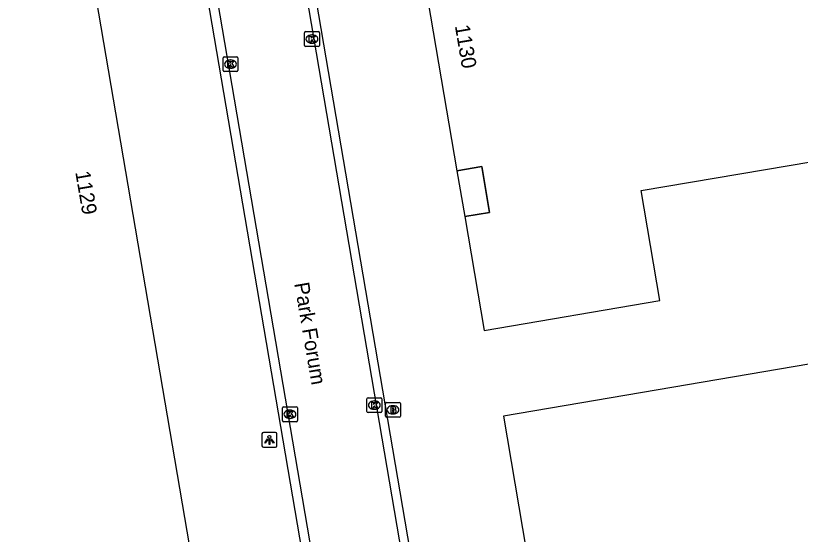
# Model space of a CAD drawing. Extents: x 154324 to 155743, y 382939 to 384183.
# Drawn here: x 154879.7 to 154932.5, y 383550.2 to 383585.1 of the extents above; entities that cross this region are included whole.
import ezdxf

# ---------------------------------------------------------------- set-up
doc = ezdxf.new("R2010")
doc.units = 0
for name, color, linetype in [('IMGEO_Brandkraan', 7, 'Continuous'), ('IMGEO_Kolk', 7, 'Continuous'), ('IMGEO_Lichtpunt', 7, 'Continuous'), ('IMGEO_Openbare_ruimte_label', 7, 'Continuous'), ('IMGEO_Pand', 7, 'Continuous'), ('IMGEO_Pand_nummerreeks', 7, 'Continuous'), ('IMGEO_Pand_overbouw', 7, 'Continuous'), ('IMGEO_Rijbaan_lokaal_gesloten', 7, 'Continuous'), ('IMGEO_Rijbaan_lokaal_open', 7, 'Continuous')]:
    doc.layers.add(name, color=color, linetype=linetype)

msp = doc.modelspace()

# ---------------------------------------------------------------- linework, layer by layer
at = {"layer": 'IMGEO_Brandkraan'}
for p, q in [((154904.624, 383558.127), (154904.624, 383558.979)), ((154904.699, 383559.053), (154905.551, 383559.053)), ((154905.112, 383558.833), (154905.137, 383558.833)), ((154905.625, 383558.979), (154905.625, 383558.127)), ((154905.551, 383558.053), (154904.699, 383558.053)), ((154905.135, 383558.273), (154905.11, 383558.273))]:
    msp.add_line(p, q, dxfattribs=at)
for points in [[(154904.624, 383558.127), (154904.624, 383558.979)], [(154904.699, 383559.053), (154905.551, 383559.053)], [(154904.972, 383558.753), (154904.972, 383558.353), (154905.185, 383558.353)], [(154905.203, 383558.753), (154904.972, 383558.753)], [(154905.151, 383558.672), (154905.097, 383558.672), (154905.097, 383558.596)], [(154905.097, 383558.596), (154905.15, 383558.596)], [(154905.625, 383558.979), (154905.625, 383558.127)], [(154905.551, 383558.053), (154904.699, 383558.053)], [(154905.159, 383558.52), (154905.097, 383558.52), (154905.097, 383558.439)], [(154905.097, 383558.439), (154905.159, 383558.439)]]:
    msp.add_lwpolyline(points, dxfattribs=at)
for centre, radius, start, end in [((154904.701, 383558.977), 0.0765, 91.552, 178.448), ((154904.701, 383558.977), 0.0765, 91.552, 178.448), ((154905.152, 383558.634), 0.0379, 267.8285, 90.9355), ((154905.207, 383558.608), 0.145, 59.4692, 91.5367), ((154905.232, 383558.655), 0.0922, 285.5137, 58.1501), ((154905.237, 383558.463), 0.105, 301.3115, 78.989), ((154905.549, 383558.977), 0.0765, 1.552, 88.448), ((154905.549, 383558.977), 0.0765, 1.552, 88.448), ((154904.701, 383558.129), 0.0765, 181.552, 268.448), ((154904.701, 383558.129), 0.0765, 181.552, 268.448), ((154905.16, 383558.479), 0.0404, 269.8759, 90.5077), ((154905.191, 383558.604), 0.251, 268.6676, 293.5347), ((154905.549, 383558.129), 0.0765, 271.552, 358.448), ((154905.549, 383558.129), 0.0765, 271.552, 358.448)]:
    msp.add_arc(centre, radius, start, end, dxfattribs=at)
for centre, major_axis, ratio, start_param, end_param in [((154905.111, 383558.553), (-0.387, 0.002), 0.722429, 4.712389, 7.853982), ((154905.136, 383558.553), (-0.39, 0.002), 0.717154, 1.570796, 4.712389)]:
    msp.add_ellipse(centre, major_axis=major_axis, ratio=ratio, start_param=start_param, end_param=end_param, dxfattribs=at)
at = {"layer": 'IMGEO_Kolk'}
for p, q in [((154899.172, 383583.091), (154899.172, 383583.943)), ((154899.247, 383584.017), (154900.099, 383584.017)), ((154900.173, 383583.943), (154900.173, 383583.091)), ((154899.66, 383583.797), (154899.685, 383583.797)), ((154900.099, 383583.017), (154899.247, 383583.017)), ((154899.683, 383583.237), (154899.658, 383583.237)), ((154893.77, 383582.329), (154894.622, 383582.329)), ((154893.695, 383581.403), (154893.695, 383582.255)), ((154894.183, 383582.109), (154894.208, 383582.109)), ((154894.696, 383582.255), (154894.696, 383581.403)), ((154894.622, 383581.329), (154893.77, 383581.329)), ((154894.206, 383581.549), (154894.181, 383581.549)), ((154903.373, 383558.443), (154903.373, 383559.295)), ((154903.448, 383559.369), (154904.3, 383559.369)), ((154903.861, 383559.149), (154903.886, 383559.149)), ((154904.374, 383559.295), (154904.374, 383558.443)), ((154897.693, 383557.83), (154897.693, 383558.682)), ((154897.768, 383558.756), (154898.62, 383558.756)), ((154898.694, 383558.682), (154898.694, 383557.83)), ((154903.884, 383558.589), (154903.859, 383558.589)), ((154898.181, 383558.536), (154898.206, 383558.536)), ((154904.3, 383558.369), (154903.448, 383558.369)), ((154898.62, 383557.756), (154897.768, 383557.756)), ((154898.204, 383557.976), (154898.179, 383557.976))]:
    msp.add_line(p, q, dxfattribs=at)
for points in [[(154899.172, 383583.091), (154899.172, 383583.943)], [(154899.247, 383584.017), (154900.099, 383584.017)], [(154900.173, 383583.943), (154900.173, 383583.091)], [(154899.493, 383583.717), (154899.616, 383583.717), (154899.616, 383583.566), (154899.746, 383583.717), (154899.91, 383583.717), (154899.764, 383583.566), (154899.917, 383583.317), (154899.765, 383583.317), (154899.68, 383583.481), (154899.616, 383583.414), (154899.616, 383583.317), (154899.493, 383583.317), (154899.493, 383583.717)], [(154900.099, 383583.017), (154899.247, 383583.017)], [(154893.77, 383582.329), (154894.622, 383582.329)], [(154893.695, 383581.403), (154893.695, 383582.255)], [(154894.016, 383582.029), (154894.139, 383582.029), (154894.139, 383581.878), (154894.269, 383582.029), (154894.433, 383582.029), (154894.287, 383581.878), (154894.44, 383581.629), (154894.288, 383581.629), (154894.203, 383581.793), (154894.139, 383581.726), (154894.139, 383581.629), (154894.016, 383581.629), (154894.016, 383582.029)], [(154894.696, 383582.255), (154894.696, 383581.403)], [(154894.622, 383581.329), (154893.77, 383581.329)], [(154903.373, 383558.443), (154903.373, 383559.295)], [(154903.448, 383559.369), (154904.3, 383559.369)], [(154904.374, 383559.295), (154904.374, 383558.443)], [(154897.693, 383557.83), (154897.693, 383558.682)], [(154897.768, 383558.756), (154898.62, 383558.756)], [(154898.694, 383558.682), (154898.694, 383557.83)], [(154903.694, 383559.069), (154903.817, 383559.069), (154903.817, 383558.918), (154903.947, 383559.069), (154904.111, 383559.069), (154903.965, 383558.918), (154904.118, 383558.669), (154903.966, 383558.669), (154903.881, 383558.833), (154903.817, 383558.766), (154903.817, 383558.669), (154903.694, 383558.669), (154903.694, 383559.069)], [(154898.014, 383558.456), (154898.137, 383558.456), (154898.137, 383558.305), (154898.267, 383558.456), (154898.431, 383558.456), (154898.285, 383558.305), (154898.438, 383558.056), (154898.286, 383558.056), (154898.201, 383558.22), (154898.137, 383558.153), (154898.137, 383558.056), (154898.014, 383558.056), (154898.014, 383558.456)], [(154904.3, 383558.369), (154903.448, 383558.369)], [(154898.62, 383557.756), (154897.768, 383557.756)]]:
    msp.add_lwpolyline(points, dxfattribs=at)
for centre, start, end in [((154899.249, 383583.941), 91.552, 178.448), ((154899.249, 383583.941), 91.552, 178.448), ((154900.097, 383583.941), 1.552, 88.448), ((154900.097, 383583.941), 1.552, 88.448), ((154899.249, 383583.093), 181.552, 268.448), ((154899.249, 383583.093), 181.552, 268.448), ((154900.097, 383583.093), 271.552, 358.448), ((154900.097, 383583.093), 271.552, 358.448), ((154893.772, 383582.253), 91.552, 178.448), ((154893.772, 383582.253), 91.552, 178.448), ((154894.62, 383582.253), 1.552, 88.448), ((154894.62, 383582.253), 1.552, 88.448), ((154893.772, 383581.405), 181.552, 268.448), ((154893.772, 383581.405), 181.552, 268.448), ((154894.62, 383581.405), 271.552, 358.448), ((154894.62, 383581.405), 271.552, 358.448), ((154903.45, 383559.293), 91.552, 178.448), ((154903.45, 383559.293), 91.552, 178.448), ((154904.298, 383559.293), 1.552, 88.448), ((154904.298, 383559.293), 1.552, 88.448), ((154897.77, 383558.68), 91.552, 178.448), ((154897.77, 383558.68), 91.552, 178.448), ((154898.618, 383558.68), 1.552, 88.448), ((154898.618, 383558.68), 1.552, 88.448), ((154903.45, 383558.445), 181.552, 268.448), ((154903.45, 383558.445), 181.552, 268.448), ((154904.298, 383558.445), 271.552, 358.448), ((154904.298, 383558.445), 271.552, 358.448), ((154897.77, 383557.832), 181.552, 268.448), ((154897.77, 383557.832), 181.552, 268.448), ((154898.618, 383557.832), 271.552, 358.448), ((154898.618, 383557.832), 271.552, 358.448)]:
    msp.add_arc(centre, 0.0765, start, end, dxfattribs=at)
for centre, major_axis, ratio, start_param, end_param in [((154899.659, 383583.517), (-0.387, 0.002), 0.722429, 4.712389, 7.853982), ((154899.684, 383583.517), (-0.39, 0.002), 0.717154, 1.570796, 4.712389), ((154894.182, 383581.829), (-0.387, 0.002), 0.722429, 4.712389, 7.853982), ((154894.207, 383581.829), (-0.39, 0.002), 0.717154, 1.570796, 4.712389), ((154903.86, 383558.869), (-0.387, 0.002), 0.722429, 4.712389, 7.853982), ((154903.885, 383558.869), (-0.39, 0.002), 0.717154, 1.570796, 4.712389), ((154898.18, 383558.256), (-0.387, 0.002), 0.722429, 4.712389, 7.853982), ((154898.205, 383558.256), (-0.39, 0.002), 0.717154, 1.570796, 4.712389)]:
    msp.add_ellipse(centre, major_axis=major_axis, ratio=ratio, start_param=start_param, end_param=end_param, dxfattribs=at)
at = {"layer": 'IMGEO_Lichtpunt'}
for p, q in [((154897.213, 383557.031), (154896.405, 383557.031)), ((154897.213, 383557.031), (154896.405, 383557.031)), ((154896.311, 383556.936), (154896.311, 383556.129)), ((154896.311, 383556.936), (154896.311, 383556.129)), ((154897.307, 383556.129), (154897.307, 383556.936)), ((154897.307, 383556.129), (154897.307, 383556.936)), ((154896.405, 383556.035), (154897.213, 383556.035)), ((154896.405, 383556.035), (154897.213, 383556.035))]:
    msp.add_line(p, q, dxfattribs=at)
for points in [[(154896.685, 383556.6), (154896.724, 383556.572), (154896.536, 383556.31), (154896.498, 383556.337), (154896.685, 383556.6)], [(154896.787, 383556.552), (154896.834, 383556.552), (154896.834, 383556.23), (154896.787, 383556.23), (154896.787, 383556.552)], [(154896.897, 383556.572), (154896.935, 383556.599), (154897.122, 383556.337), (154897.083, 383556.309), (154896.897, 383556.572)]]:
    msp.add_lwpolyline(points, dxfattribs=at)
msp.add_circle((154896.81, 383556.734), 0.0994, dxfattribs=at)
for centre, start, end in [((154896.405, 383556.936), 90, 180), ((154896.405, 383556.936), 90, 180), ((154897.213, 383556.936), 0, 90), ((154897.213, 383556.936), 0, 90), ((154896.405, 383556.129), 180, 270), ((154896.405, 383556.129), 180, 270), ((154897.213, 383556.129), 270, 0), ((154897.213, 383556.129), 270, 360)]:
    msp.add_arc(centre, 0.0946, start, end, dxfattribs=at)
at = {"layer": 'IMGEO_Pand'}
for points in [[(154879.183, 383621.215), (154895.555, 383525.105), (154815.631, 383511.491), (154769.142, 383503.586), (154738.941, 383498.446)], [(154950.869, 383602.597), (154905.966, 383594.94), (154906.281, 383593.097), (154907.891, 383593.369), (154908.556, 383589.425), (154906.953, 383589.16), (154909.434, 383574.645), (154911.095, 383574.942), (154911.63, 383571.85), (154909.961, 383571.564), (154911.271, 383563.897), (154923.094, 383565.904), (154921.833, 383573.322), (154954.895, 383578.906), (154950.869, 383602.597)], [(154942.463, 383563.229), (154912.559, 383558.136), (154923.822, 383491.524), (154938.938, 383494.079), (154939.875, 383488.538), (154924.759, 383485.982), (154924.851, 383485.44), (154964.694, 383492.169), (154960.716, 383515.618), (154950.858, 383513.939), (154942.463, 383563.229)]]:
    msp.add_lwpolyline(points, dxfattribs=at)
at = {"layer": 'IMGEO_Pand_overbouw'}
msp.add_lwpolyline([(154909.961, 383571.564), (154911.63, 383571.85), (154911.095, 383574.942), (154909.434, 383574.645)], close=True, dxfattribs=at)
at = {"layer": 'IMGEO_Rijbaan_lokaal_gesloten'}
for points in [[(154859.21, 383821.776), (154860.592, 383813.666), (154872.994, 383740.868), (154875.261, 383727.607), (154875.734, 383724.688), (154937.891, 383359.922)], [(154854.425, 383814.31), (154854.653, 383812.991), (154854.813, 383812.024), (154858.483, 383790.497), (154869.559, 383725.258), (154869.596, 383725.133), (154932.04, 383358.964)]]:
    msp.add_lwpolyline(points, dxfattribs=at)
at = {"layer": 'IMGEO_Rijbaan_lokaal_open'}
for points in [[(154936.699, 383370.542), (154936.688, 383370.604), (154886.005, 383668.098)], [(154931.446, 383358.867), (154880.326, 383658.587), (154880.297, 383658.755)]]:
    msp.add_lwpolyline(points, dxfattribs=at)

# ---------------------------------------------------------------- texts
at = {"layer": 'IMGEO_Openbare_ruimte_label'}
msp.add_text('Park Forum', height=1, rotation=279.6695, dxfattribs=at).set_placement((154898.481, 383567.06))
at = {"layer": 'IMGEO_Pand_nummerreeks'}
for s, rotation, p in [('1130', 279.7, (154909.287, 383584.405)), ('1129', 279.7573, (154883.744, 383574.557))]:
    msp.add_text(s, height=1, rotation=rotation, dxfattribs=at).set_placement(p)

doc.saveas('drawing.dxf')
